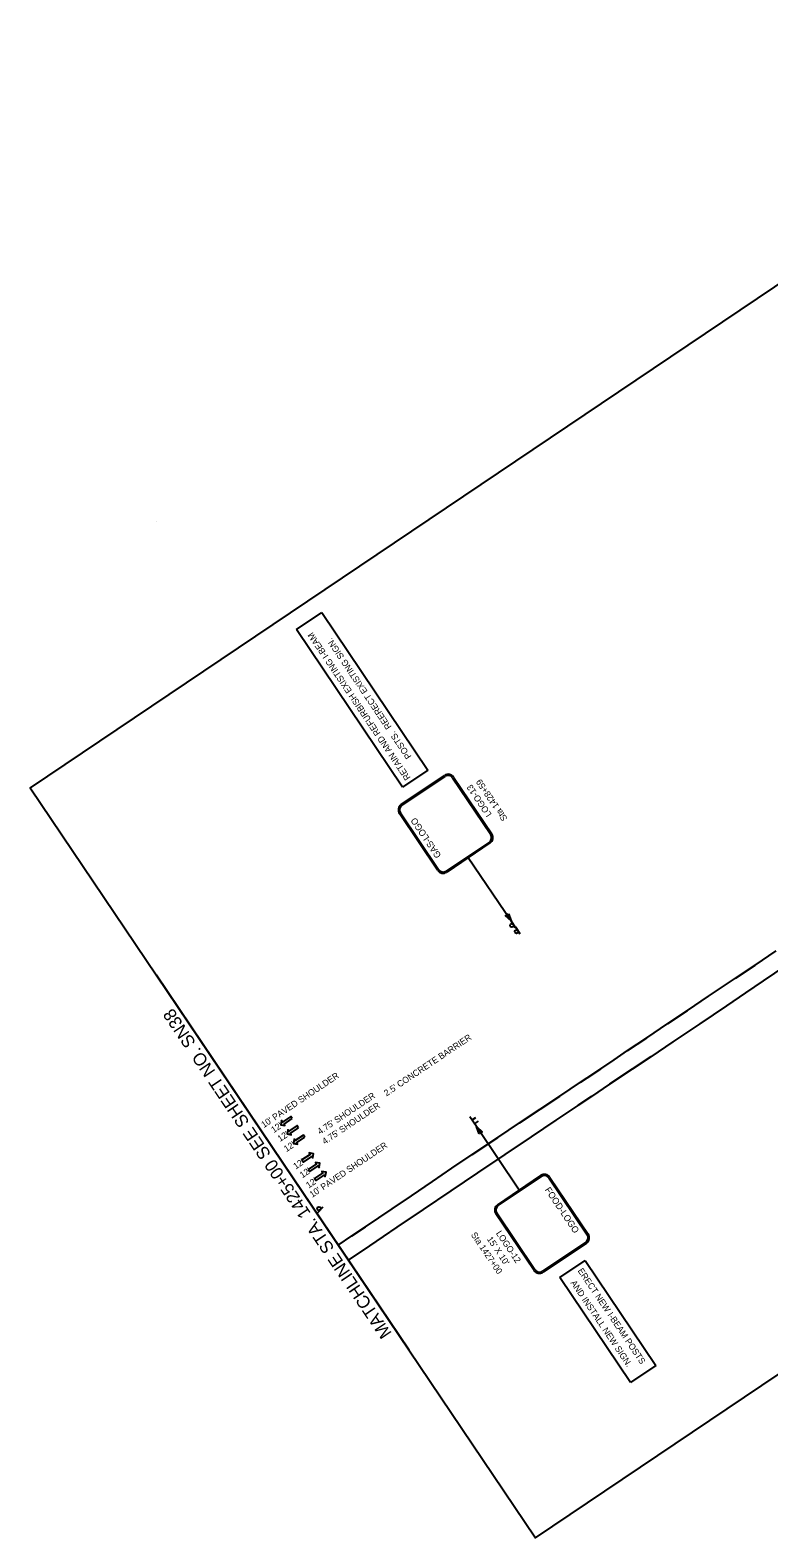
# Model space of a CAD drawing. Extents: x 1790709 to 1792453, y 1184078 to 1185781.
# Drawn here: x 1790709 to 1791525, y 1184078 to 1185745 of the extents above; entities that cross this region are included whole.
import ezdxf

# ---------------------------------------------------------------- set-up
doc = ezdxf.new("R2010")
doc.units = 0
for name, color, linetype in [('RD_EX_Road', 7, 'Continuous'), ('RD_PD_Final_LnLine', 7, 'Continuous'), ('RD_PD_Final_TX', 7, 'Continuous'), ('RD_SHT_MatchLine', 7, 'Continuous'), ('RD_SHT_ShtClip', 7, 'Continuous'), ('SN_P_Signs', 7, 'Continuous')]:
    doc.layers.add(name, color=color, linetype=linetype)

# ---------------------------------------------------------------- blocks, each defined once
blk = doc.blocks.new('SARRW2')
at = {"layer": 'RD_PD_Final_LnLine'}
blk.add_lwpolyline([(-12, 1.2), (-12, -1.2), (-2.8, -1.2), (-2.8, -2.8), (0, 0), (-2.8, 2.8), (-2.8, 1.2)], close=True, dxfattribs=at)

msp = doc.modelspace()

# ---------------------------------------------------------------- linework, layer by layer
at = {"layer": 'RD_EX_Road'}
for points in [[(1791049.3, 1184401.5), (1791064.4, 1184411.8), (1791079.3, 1184421.8), (1791108.9, 1184441.7), (1791130.2, 1184456.1), (1791153.6, 1184472.1), (1791174.9, 1184486.5), (1791197.4, 1184501.6), (1791225.7, 1184520.7), (1791249.7, 1184536.7), (1791272.3, 1184551.8), (1791294.1, 1184566.4), (1791317, 1184581.6), (1791324.3, 1184586.4), (1791339.5, 1184596.5), (1791354.3, 1184606.6), (1791369.1, 1184616.6), (1791390.2, 1184630.8), (1791413.5, 1184646.5), (1791435.3, 1184661.2), (1791458.4, 1184676.7), (1791488.2, 1184696.6), (1791510, 1184711.3), (1791533.3, 1184727.1)], [(1791544, 1184710.6), (1791519.1, 1184693.7), (1791499.5, 1184680.4), (1791478.6, 1184666.3), (1791449, 1184646.3), (1791419, 1184626.2), (1791394.6, 1184609.9), (1791374, 1184596.2), (1791349.1, 1184579.4), (1791329.2, 1184566.1), (1791313.9, 1184555.8), (1791289.9, 1184539.9), (1791262.6, 1184521.5), (1791233.3, 1184501.7), (1791203.1, 1184481.4), (1791173.7, 1184461.5), (1791143.2, 1184441), (1791113.9, 1184421.3), (1791083.8, 1184400.9), (1791060.3, 1184385.1)]]:
    msp.add_lwpolyline(points, dxfattribs=at)
at = {"layer": 'RD_SHT_MatchLine'}
msp.add_lwpolyline([(1791127.5, 1184285.3), (1790987.9, 1184492.7), (1790848.3, 1184700)], dxfattribs=at)
at = {"layer": 'RD_SHT_ShtClip'}
msp.add_lwpolyline([(1791845.3, 1184467.1), (1791786.7, 1184554.2), (1792452.8, 1185002.6), (1791953, 1185745.1), (1791953, 1185745.1), (1790708.7, 1184907.4), (1791267.1, 1184077.9)], close=True, dxfattribs=at)
at = {"layer": 'SN_P_Signs'}
for p, q in [((1790848.1, 1185201.5), (1790848.1, 1185201.5)), ((1791003.1, 1185082.2), (1791031, 1185101)), ((1791031, 1185101), (1791148.3, 1184926.7)), ((1791120.4, 1184908), (1791003.1, 1185082.2)), ((1791148.3, 1184926.7), (1791120.4, 1184908)), ((1791193, 1184830.2), (1791240.3, 1184760)), ((1791245.3, 1184752.5), (1791240.3, 1184760)), ((1791250.5, 1184745.6), (1791245.5, 1184753)), ((1791202.1, 1184532.6), (1791194.8, 1184543.4)), ((1791197.1, 1184540), (1791201.3, 1184542.8)), ((1791199.9, 1184535.8), (1791204.1, 1184538.6)), ((1791249.4, 1184462.4), (1791202.1, 1184532.6)), ((1791026.2, 1184437.4), (1791032.5, 1184443.8)), ((1791294.1, 1184365.8), (1791322, 1184384.6)), ((1791322, 1184384.6), (1791400.2, 1184268.4)), ((1791372.3, 1184249.7), (1791294.1, 1184365.8)), ((1791400.2, 1184268.4), (1791372.3, 1184249.7))]:
    msp.add_line(p, q, dxfattribs=at)
for points in [[(1791118.9, 1184888.8), (1791166.7, 1184920.9)], [(1791119.6, 1184887.8), (1791167.3, 1184919.9)], [(1791175.7, 1184918.3), (1791217.9, 1184855.6)], [(1791176.7, 1184919), (1791218.9, 1184856.3)], [(1791159.1, 1184816.1), (1791116.9, 1184878.8)], [(1791160.1, 1184816.7), (1791117.9, 1184879.4)], [(1791216.3, 1184847.3), (1791168.5, 1184815.1)], [(1791216.9, 1184846.3), (1791169.1, 1184814.1)], [(1791225.5, 1184446.3), (1791273.2, 1184478.5)], [(1791226.1, 1184445.3), (1791273.9, 1184477.5)], [(1791282.2, 1184475.8), (1791324.5, 1184413.1)], [(1791283.2, 1184476.5), (1791325.5, 1184413.8)], [(1791265.7, 1184373.6), (1791223.5, 1184436.3)], [(1791266.7, 1184374.3), (1791224.5, 1184437)], [(1791322.8, 1184404.8), (1791275.1, 1184372.6)], [(1791323.5, 1184403.8), (1791275.7, 1184371.6)]]:
    msp.add_lwpolyline(points, dxfattribs=at)
for points in [[(1791237.4, 1184767.9), (1791240.3, 1184760), (1791234, 1184765.6)], [(1791205, 1184524.6), (1791202.1, 1184532.6), (1791208.4, 1184526.9)]]:
    msp.add_lwpolyline(points, close=True, dxfattribs=at)
for centre in [(1791241.1, 1184755.1), (1791246.3, 1184748.2), (1791027.9, 1184442)]:
    msp.add_circle(centre, 2, dxfattribs=at)
for centre, radius, start, end in [((1791170.7, 1184915), 7.2, 33.9476, 123.9476), ((1791170.7, 1184915), 6, 33.9476, 123.9476), ((1791122.9, 1184882.8), 7.2, 123.9476, 213.9476), ((1791122.9, 1184882.8), 6, 123.9476, 213.9476), ((1791212.9, 1184852.2), 6, 303.9476, 33.9476), ((1791212.9, 1184852.2), 7.2, 303.9476, 33.9476), ((1791165.1, 1184820.1), 7.2, 213.9476, 303.9476), ((1791165.1, 1184820.1), 6, 213.9476, 303.9476), ((1791277.3, 1184472.5), 7.2, 33.9476, 123.9476), ((1791277.3, 1184472.5), 6, 33.9476, 123.9476), ((1791229.5, 1184440.3), 7.2, 123.9476, 213.9476), ((1791229.5, 1184440.3), 6, 123.9476, 213.9476), ((1791319.5, 1184409.8), 6, 303.9476, 33.9476), ((1791319.5, 1184409.8), 7.2, 303.9476, 33.9476), ((1791271.7, 1184377.6), 7.2, 213.9476, 303.9476), ((1791271.7, 1184377.6), 6, 213.9476, 303.9476)]:
    msp.add_arc(centre, radius, start, end, dxfattribs=at)

# ---------------------------------------------------------------- block references
at = {"layer": 'RD_PD_Final_LnLine', "xscale": 1.1999999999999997}
for p, yscale, rotation in [((1790985.7, 1184534.6), 1.2000000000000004, -146.05256015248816), ((1790992.6, 1184524.5), 1.2000000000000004, -146.05256015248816), ((1790999.6, 1184514.1), 1.2000000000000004, -146.05256015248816), ((1791021.9, 1184502.6), 1.2, 33.94743984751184), ((1791028.9, 1184492.2), 1.2, 33.94743984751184), ((1791035.8, 1184482.1), 1.2, 33.94743984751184)]:
    msp.add_blockref('SARRW2', p, dxfattribs=dict(at, yscale=yscale, rotation=rotation))

# ---------------------------------------------------------------- texts
at = {"layer": 'RD_PD_Final_TX'}
for s, p in [("2.5' CONCRETE BARRIER", (1791102.6, 1184565.9)), ("10' PAVED SHOULDER", (1790967, 1184530.9)), ("4.75' SHOULDER", (1791029, 1184523.5)), ("4.75' SHOULDER", (1791034.4, 1184512.6)), ("12'", (1790977.9, 1184525.3)), ("12'", (1790985, 1184515.6)), ("12'", (1790992, 1184504.3)), ("10' PAVED SHOULDER", (1791020.4, 1184453.8)), ("12'", (1791002.4, 1184485.1)), ("12'", (1791009.6, 1184475.4)), ("12'", (1791016.5, 1184464.1))]:
    msp.add_text(s, height=7, rotation=33.9474, dxfattribs=at).set_placement(p)
at = {"layer": 'RD_SHT_MatchLine'}
msp.add_text('MATCHLINE STA. 1425+00 SEE SHEET NO. SN38', height=14, rotation=123.9476, dxfattribs=at).set_placement((1791108.8, 1184304.1))
at = {"layer": 'SN_P_Signs'}
for s, height, rotation, p in [('RETAIN AND REFURBISH EXISTING I-BEAM', 7, 123.9477, (1791129.4, 1184918.5)), ('POSTS.  REERECT EXISTING SIGN.', 7, 123.9477, (1791130.5, 1184942)), ('Sta 1428+59', 7, 123.9477, (1791236.6, 1184873.4)), ('LOGO-13', 7, 123.9477, (1791219.2, 1184878)), ('GAS-LOGO', 7.2, 123.9476, (1791163.4, 1184832.5)), ('FOOD-LOGO', 7.2, 303.9476, (1791277.2, 1184462.7)), ('Sta 1427+00', 7, 303.9477, (1791195.6, 1184413)), ('LOGO-12', 7, 303.9477, (1791223.2, 1184414.6)), ("15' X 10'", 7, 303.9477, (1791213.2, 1184408.2)), ('ERECT NEW I-BEAM POSTS', 7, 303.9477, (1791313.6, 1184373.2)), ('AND INSTALL NEW SIGN.', 7, 303.9477, (1791305.7, 1184359.8))]:
    msp.add_text(s, height=height, rotation=rotation, dxfattribs=at).set_placement(p)

doc.saveas('drawing.dxf')
